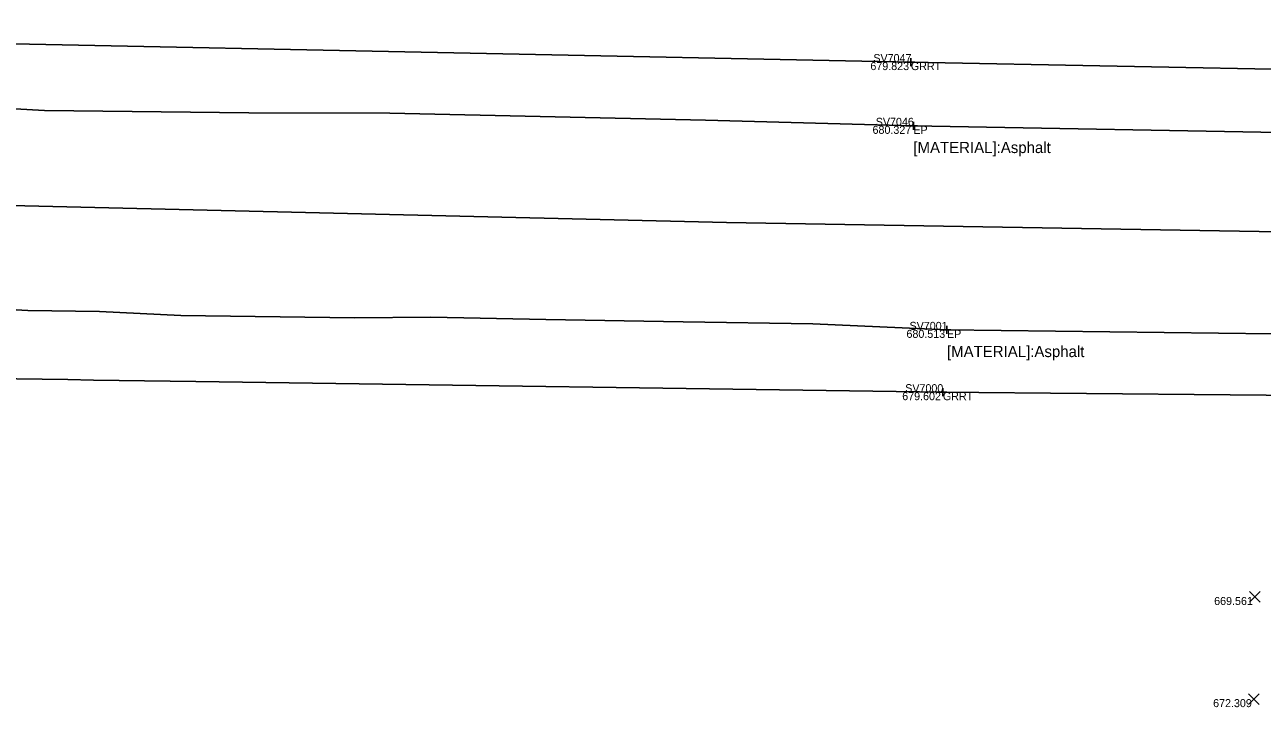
# Model space of a CAD drawing. Extents: x 1659932 to 1663108, y 619867 to 620611.
# Drawn here: x 1660482.2 to 1660636.8, y 620187 to 620272.2 of the extents above; entities that cross this region are included whole.
import ezdxf

# ---------------------------------------------------------------- set-up
doc = ezdxf.new("R2010")
doc.units = 0
for name, color, linetype in [('PM_X_CL_Dashed', 7, 'Continuous'), ('PV_X_EOP', 7, 'Continuous'), ('RD_X_GR_Lt', 7, 'Continuous'), ('RD_X_GR_Rt', 7, 'Continuous'), ('SV_X_Random_Point', 7, 'Continuous'), ('SV_X_Shot_Marker', 7, 'Continuous'), ('SV_X_Text', 7, 'Continuous'), ('SV_X_Text_Comment', 7, 'Continuous'), ('SV_X_Text_Elevation', 7, 'Continuous'), ('SV_X_Text_Name', 7, 'Continuous')]:
    doc.layers.add(name, color=color, linetype=linetype)

msp = doc.modelspace()

# ---------------------------------------------------------------- linework, layer by layer
at = {"layer": 'PM_X_CL_Dashed'}
msp.add_lwpolyline([(1660473.33, 620249.8), (1660569.82, 620247.52), (1660683.17, 620245.58), (1660845.9, 620242.37), (1660966.03, 620239.29), (1661085.35, 620237.14), (1661180.4, 620235.01), (1661204.65, 620234.52)], dxfattribs=at)
at = {"layer": 'PV_X_EOP'}
for points in [[(1660593.17, 620259.57), (1660567.21, 620260.29), (1660527.75, 620261.15), (1660510.16, 620261.19), (1660484.61, 620261.47), (1660473.45, 620262.09)], [(1661208.92, 620246.9), (1661156.94, 620248.21), (1661087.29, 620250.6), (1661037.39, 620250.48), (1660981.01, 620252.16), (1660916.41, 620253.34), (1660855.2, 620254.44), (1660801.44, 620255.57), (1660749.64, 620256.49), (1660700.03, 620257.78), (1660643.44, 620258.64), (1660593.17, 620259.57)], [(1660597.37, 620234.1), (1660580.6, 620234.85), (1660564.4, 620235.11), (1660547.24, 620235.39), (1660532.89, 620235.68), (1660523.35, 620235.6), (1660501.64, 620235.89), (1660491.51, 620236.41), (1660482.53, 620236.51), (1660473.02, 620237.05)], [(1660597.37, 620234.1), (1660651.64, 620233.44), (1660703.42, 620232.61), (1660757.32, 620231.35), (1660809.76, 620230.12), (1660857.03, 620229.26), (1660910.07, 620228.44), (1660968.25, 620227.38), (1661028.27, 620226.15), (1661081.58, 620225.11), (1661140.41, 620223.53), (1661201.71, 620222.7)]]:
    msp.add_lwpolyline(points, dxfattribs=at)
at = {"layer": 'RD_X_GR_Lt'}
for p, q in [((1660363.83, 620272.19), (1660592.86, 620267.53)), ((1660596.86, 620226.32), (1660503.51, 620227.66))]:
    msp.add_line(p, q, dxfattribs=at)
msp.add_arc((1660533.65, 622926.05), 2698.56, 265.01858, 269.36013, dxfattribs=at)
at = {"layer": 'RD_X_GR_Rt'}
for points in [[(1661224.69, 620250.79), (1661156.18, 620253.35), (1661087.54, 620257.19), (1661037.26, 620258.5), (1660981.37, 620259.47), (1660918.68, 620260.81), (1660856.77, 620262.08), (1660800.7, 620262.74), (1660750.31, 620264.54), (1660700.27, 620265.16), (1660644.43, 620266.52), (1660592.86, 620267.53)], [(1660596.86, 620226.32), (1660650.68, 620225.81), (1660702.7, 620224.83), (1660759.05, 620223.97), (1660808.86, 620222.78), (1660856.77, 620221.69), (1660908.98, 620220.55), (1660971.26, 620219.59), (1661027.54, 620217.92), (1661083.51, 620217.29), (1661139.61, 620218.11), (1661215.13, 620218.24)]]:
    msp.add_lwpolyline(points, dxfattribs=at)
at = {"layer": 'SV_X_Random_Point'}
for p, q in [((1660635.17, 620200.09), (1660636.5, 620201.42)), ((1660635.17, 620201.42), (1660636.5, 620200.09)), ((1660635.03, 620187.33), (1660636.37, 620188.67)), ((1660635.03, 620188.67), (1660636.37, 620187.33))]:
    msp.add_line(p, q, dxfattribs=at)
at = {"layer": 'SV_X_Shot_Marker'}
for p, q in [((1660592.36, 620267.53), (1660593.36, 620267.53)), ((1660592.86, 620268.03), (1660592.86, 620267.03)), ((1660592.86, 620267.53), (1660592.86, 620267.53)), ((1660592.67, 620259.57), (1660593.67, 620259.57)), ((1660593.17, 620260.07), (1660593.17, 620259.07)), ((1660593.17, 620259.57), (1660593.17, 620259.57)), ((1660597.37, 620234.6), (1660597.37, 620233.6)), ((1660596.87, 620234.1), (1660597.87, 620234.1)), ((1660597.37, 620234.1), (1660597.37, 620234.1)), ((1660596.86, 620226.82), (1660596.86, 620225.82)), ((1660596.36, 620226.32), (1660597.36, 620226.32)), ((1660596.86, 620226.32), (1660596.86, 620226.32))]:
    msp.add_line(p, q, dxfattribs=at)

# ---------------------------------------------------------------- texts
at = {"layer": 'SV_X_Text'}
for p in [(1660593.17, 620256.17), (1660597.37, 620230.7)]:
    msp.add_text('[MATERIAL]:Asphalt', height=1.4, dxfattribs=at).set_placement(p)
at = {"layer": 'SV_X_Text_Comment'}
for s, p in [('GRRT', (1660592.86, 620266.53)), ('EP', (1660593.17, 620258.57)), ('EP', (1660597.37, 620233.1)), ('GRRT', (1660596.86, 620225.32))]:
    msp.add_text(s, height=1, dxfattribs=at).set_placement(p)
at = {"layer": 'SV_X_Text_Elevation'}
for s, p in [('679.823', (1660587.8, 620266.53)), ('680.327', (1660588.07, 620258.57)), ('680.513', (1660592.31, 620233.1)), ('679.602', (1660591.78, 620225.32)), ('669.561', (1660630.75, 620199.75)), ('672.309', (1660630.62, 620187))]:
    msp.add_text(s, height=1, dxfattribs=at).set_placement(p)
at = {"layer": 'SV_X_Text_Name'}
for s, p in [('SV7047', (1660588.17, 620267.53)), ('SV7046', (1660588.47, 620259.57)), ('SV7001', (1660592.69, 620234.1)), ('SV7000', (1660592.15, 620226.32))]:
    msp.add_text(s, height=1, dxfattribs=at).set_placement(p)

doc.saveas('drawing.dxf')
